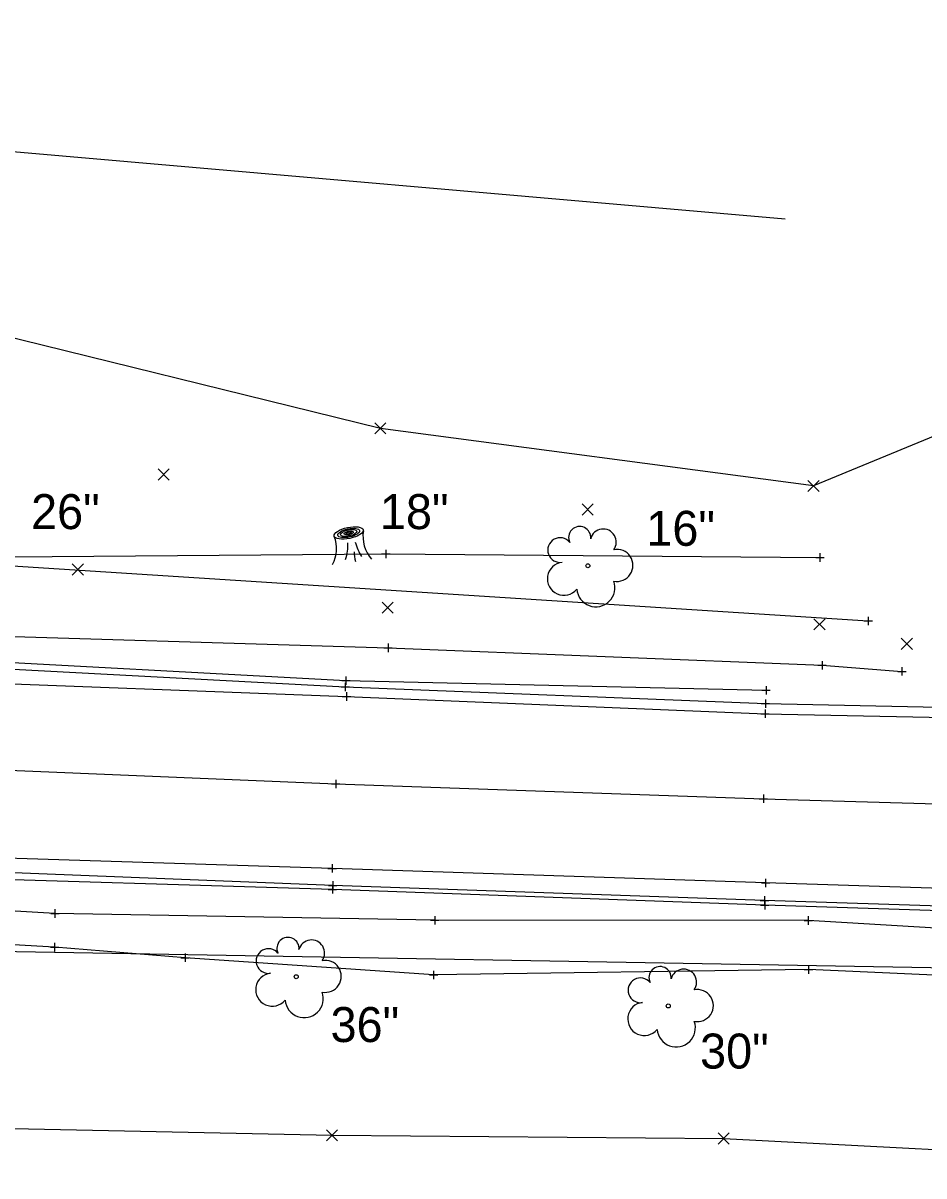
# Model space of a CAD drawing. Extents: x 2005176 to 2005823, y 572472 to 572942.
# Drawn here: x 2005639.9 to 2005747.1, y 572557 to 572694.3 of the extents above; entities that cross this region are included whole.
import ezdxf

# ---------------------------------------------------------------- set-up
doc = ezdxf.new("R2010")
doc.units = 0
for name, color, linetype in [('GE_X_Alignment_1000_Bearings', 7, 'Continuous'), ('GE_X_Alignment_100_Bearings', 7, 'Continuous'), ('GE_X_Alignment_100_Cardinal_Points', 7, 'Continuous'), ('GE_X_Alignment_100_Distances', 7, 'Continuous'), ('GE_X_Alignment_100_Stations', 7, 'Continuous'), ('GE_X_Alignment_500_Bearings', 7, 'Continuous'), ('GE_X_Alignment_500_Cardinal_Points', 7, 'Continuous'), ('GE_X_Alignment_500_Distances', 7, 'Continuous'), ('SC_Scratch10', 7, 'Continuous'), ('SC_Scratch8', 7, 'Continuous'), ('SV_P_Mon_Cells_Set', 7, 'Continuous'), ('SV_X_Random_Point', 7, 'Continuous'), ('SV_X_Shot_Marker', 7, 'Continuous'), ('SV_X_Terrain_Boundary', 7, 'Continuous'), ('UT_X_Overhead_Electric', 7, 'Continuous'), ('UT_X_Overhead_Telecom', 7, 'Continuous'), ('VG_X_Text', 7, 'Continuous')]:
    doc.layers.add(name, color=color, linetype=linetype)

msp = doc.modelspace()

# ---------------------------------------------------------------- linework, layer by layer
at = {"layer": 'GE_X_Alignment_1000_Bearings'}
msp.add_lwpolyline([(2005377.36, 572646.47), (2005740.51, 572623.1)], dxfattribs=at)
at = {"layer": 'GE_X_Alignment_100_Bearings'}
for points in [[(2005220.7, 572626.42), (2005272.19, 572624.71), (2005322.24, 572623.5), (2005370.59, 572622.7), (2005425.14, 572621.65), (2005477.36, 572620.84), (2005525.07, 572619.6), (2005576.7, 572617.86), (2005628.14, 572615.99), (2005678.39, 572614.09), (2005728.23, 572612.03), (2005777.04, 572611.02), (2005819.95, 572609.99)], [(2005818.64, 572588.97), (2005775.2, 572590.4), (2005728.29, 572591.88), (2005676.68, 572593.61), (2005626.55, 572595.19), (2005577.83, 572596.72), (2005526.97, 572598.44), (2005477.01, 572599.53), (2005423.67, 572600.7), (2005368.75, 572601.99), (2005321.74, 572602.99), (2005266.72, 572604.35), (2005220.03, 572605.66)]]:
    msp.add_lwpolyline(points, dxfattribs=at)
at = {"layer": 'GE_X_Alignment_100_Cardinal_Points'}
msp.add_lwpolyline([(2005220.5, 572615.99), (2005272.51, 572614.37), (2005322.2, 572613.2), (2005370.62, 572612.29), (2005424.94, 572611.27), (2005476.5, 572610.17), (2005524.32, 572608.79), (2005576.49, 572607.4), (2005627.69, 572605.77), (2005677.11, 572603.68), (2005728.03, 572601.92), (2005776.18, 572600.5), (2005820.14, 572599.28)], dxfattribs=at)
at = {"layer": 'GE_X_Alignment_100_Distances'}
for points in [[(2005220.68, 572626.38), (2005272.19, 572624.71), (2005322.24, 572623.5), (2005370.59, 572622.7), (2005425.14, 572621.65), (2005477.36, 572620.84), (2005525.07, 572619.6), (2005576.7, 572617.86), (2005628.14, 572615.99), (2005678.39, 572614.09), (2005728.23, 572612.03), (2005777.04, 572611.02), (2005820.02, 572609.9)], [(2005818.7, 572589.05), (2005775.2, 572590.4), (2005728.29, 572591.88), (2005676.68, 572593.61), (2005626.55, 572595.19), (2005577.83, 572596.72), (2005526.97, 572598.44), (2005477.01, 572599.53), (2005423.67, 572600.7), (2005368.75, 572601.99), (2005321.74, 572602.99), (2005266.72, 572604.35), (2005220.06, 572605.65)]]:
    msp.add_lwpolyline(points, dxfattribs=at)
at = {"layer": 'GE_X_Alignment_100_Stations'}
for points in [[(2005525.52, 572638.81), (2005532.8, 572636.84), (2005542.1, 572631.82), (2005552.86, 572627.27), (2005580.9, 572624.65), (2005628.27, 572621.55), (2005683.34, 572619.89), (2005735.02, 572617.81), (2005744.53, 572617.08)], [(2005818.32, 572583.75), (2005776.41, 572584.84), (2005733.38, 572587.41), (2005688.89, 572587.43), (2005643.67, 572588.24), (2005617.3, 572589.8), (2005601, 572590.26), (2005586.78, 572589.84), (2005574.29, 572588.4), (2005565.07, 572583.34)]]:
    msp.add_lwpolyline(points, dxfattribs=at)
at = {"layer": 'GE_X_Alignment_500_Bearings'}
msp.add_lwpolyline([(2005563.28, 572631.16), (2005581.34, 572632.07), (2005628.4, 572630.65), (2005683.07, 572631.08), (2005734.76, 572630.65)], dxfattribs=at)
at = {"layer": 'GE_X_Alignment_500_Cardinal_Points'}
msp.add_lwpolyline([(2005818.94, 572578.27), (2005776.52, 572579.63), (2005733.4, 572581.57), (2005688.76, 572580.93), (2005659.16, 572582.97), (2005643.63, 572584.23), (2005617.78, 572585.7), (2005598.98, 572587.73), (2005575.61, 572583.45)], dxfattribs=at)
at = {"layer": 'GE_X_Alignment_500_Distances'}
msp.add_lwpolyline([(2005220.4, 572616.04), (2005272.51, 572614.37), (2005322.2, 572613.2), (2005370.62, 572612.29), (2005424.94, 572611.27), (2005476.5, 572610.17), (2005524.32, 572608.79), (2005576.49, 572607.4), (2005627.69, 572605.77), (2005677.11, 572603.68), (2005728.03, 572601.92), (2005776.18, 572600.5), (2005820.14, 572599.26)], dxfattribs=at)
at = {"layer": 'SC_Scratch10'}
for points in [[(2005220.88, 572629.15), (2005272.14, 572627.64), (2005321.83, 572626.68), (2005370.65, 572626), (2005424.7, 572625.92), (2005476.69, 572625.33), (2005525.49, 572622.56), (2005576.48, 572620.99), (2005628.3, 572618.68), (2005678.32, 572615.98), (2005728.35, 572614.83)], [(2005818.55, 572585.94), (2005774.93, 572587.72), (2005728.19, 572589.23), (2005676.71, 572591.12), (2005626.89, 572592.62), (2005577.77, 572593.78), (2005527.62, 572595.75), (2005477.17, 572596.25), (2005467.62, 572596.6)]]:
    msp.add_lwpolyline(points, dxfattribs=at)
at = {"layer": 'SC_Scratch8'}
for points in [[(2005220.9, 572628.72), (2005272.16, 572627.13), (2005321.83, 572625.74), (2005370.81, 572625), (2005424.98, 572624.56), (2005477.31, 572623.7), (2005525.21, 572621.63), (2005576.56, 572620.01), (2005628.24, 572617.89), (2005678.25, 572615.23), (2005728.27, 572613.25), (2005777.12, 572612.24), (2005820.02, 572611.5)], [(2005818.66, 572586.64), (2005775.01, 572588.28), (2005728.16, 572589.79), (2005676.75, 572591.58), (2005626.73, 572593.57), (2005577.92, 572595.76), (2005527.42, 572597.32), (2005476.91, 572598.65), (2005423.43, 572599.27), (2005368.77, 572600.6), (2005321.59, 572601.67), (2005267.03, 572602.73), (2005220.03, 572603.93)]]:
    msp.add_lwpolyline(points, dxfattribs=at)
at = {"layer": 'SV_P_Mon_Cells_Set'}
for p, q in [((2005682.57, 572631.08), (2005683.57, 572631.08)), ((2005683.07, 572631.58), (2005683.07, 572630.58)), ((2005683.07, 572631.08), (2005683.07, 572631.08)), ((2005734.76, 572631.15), (2005734.76, 572630.15)), ((2005734.26, 572630.65), (2005735.26, 572630.65)), ((2005734.76, 572630.65), (2005734.76, 572630.65)), ((2005740.01, 572623.1), (2005741.01, 572623.1)), ((2005740.51, 572623.6), (2005740.51, 572622.6)), ((2005740.51, 572623.1), (2005740.51, 572623.1)), ((2005682.84, 572619.89), (2005683.84, 572619.89)), ((2005683.34, 572620.39), (2005683.34, 572619.39)), ((2005683.34, 572619.89), (2005683.34, 572619.89)), ((2005735.02, 572618.31), (2005735.02, 572617.31)), ((2005734.52, 572617.81), (2005735.52, 572617.81)), ((2005735.02, 572617.81), (2005735.02, 572617.81)), ((2005744.03, 572617.08), (2005745.03, 572617.08)), ((2005744.53, 572617.58), (2005744.53, 572616.58)), ((2005744.53, 572617.08), (2005744.53, 572617.08)), ((2005677.82, 572615.98), (2005678.82, 572615.98)), ((2005678.25, 572615.73), (2005678.25, 572614.73)), ((2005678.32, 572616.48), (2005678.32, 572615.48)), ((2005678.32, 572615.98), (2005678.32, 572615.98)), ((2005677.75, 572615.23), (2005678.75, 572615.23)), ((2005678.25, 572615.23), (2005678.25, 572615.23)), ((2005678.39, 572614.59), (2005678.39, 572613.59)), ((2005678.39, 572614.59), (2005678.39, 572613.59)), ((2005727.85, 572614.83), (2005728.85, 572614.83)), ((2005728.35, 572615.33), (2005728.35, 572614.33)), ((2005728.35, 572614.83), (2005728.35, 572614.83)), ((2005677.89, 572614.09), (2005678.89, 572614.09)), ((2005677.89, 572614.09), (2005678.89, 572614.09)), ((2005678.39, 572614.09), (2005678.39, 572614.09)), ((2005678.39, 572614.09), (2005678.39, 572614.09)), ((2005727.77, 572613.25), (2005728.77, 572613.25)), ((2005728.27, 572613.75), (2005728.27, 572612.75)), ((2005728.27, 572613.25), (2005728.27, 572613.25)), ((2005727.73, 572612.03), (2005728.73, 572612.03)), ((2005727.73, 572612.03), (2005728.73, 572612.03)), ((2005728.23, 572612.53), (2005728.23, 572611.53)), ((2005728.23, 572612.53), (2005728.23, 572611.53)), ((2005728.23, 572612.03), (2005728.23, 572612.03)), ((2005728.23, 572612.03), (2005728.23, 572612.03)), ((2005676.61, 572603.68), (2005677.61, 572603.68)), ((2005676.61, 572603.68), (2005677.61, 572603.68)), ((2005677.11, 572604.18), (2005677.11, 572603.18)), ((2005677.11, 572604.18), (2005677.11, 572603.18)), ((2005677.11, 572603.68), (2005677.11, 572603.68)), ((2005677.11, 572603.68), (2005677.11, 572603.68)), ((2005727.53, 572601.92), (2005728.53, 572601.92)), ((2005727.53, 572601.92), (2005728.53, 572601.92)), ((2005728.03, 572602.42), (2005728.03, 572601.42)), ((2005728.03, 572602.42), (2005728.03, 572601.42)), ((2005728.03, 572601.92), (2005728.03, 572601.92)), ((2005728.03, 572601.92), (2005728.03, 572601.92)), ((2005676.18, 572593.61), (2005677.18, 572593.61)), ((2005676.18, 572593.61), (2005677.18, 572593.61)), ((2005676.68, 572594.11), (2005676.68, 572593.11)), ((2005676.68, 572594.11), (2005676.68, 572593.11)), ((2005676.68, 572593.61), (2005676.68, 572593.61)), ((2005676.68, 572593.61), (2005676.68, 572593.61)), ((2005728.29, 572592.38), (2005728.29, 572591.38)), ((2005728.29, 572592.38), (2005728.29, 572591.38)), ((2005676.21, 572591.12), (2005677.21, 572591.12)), ((2005676.25, 572591.58), (2005677.25, 572591.58)), ((2005676.71, 572591.62), (2005676.71, 572590.62)), ((2005676.71, 572591.12), (2005676.71, 572591.12)), ((2005676.75, 572592.08), (2005676.75, 572591.08)), ((2005676.75, 572591.58), (2005676.75, 572591.58)), ((2005727.79, 572591.88), (2005728.79, 572591.88)), ((2005727.79, 572591.88), (2005728.79, 572591.88)), ((2005728.29, 572591.88), (2005728.29, 572591.88)), ((2005728.29, 572591.88), (2005728.29, 572591.88)), ((2005727.66, 572589.79), (2005728.66, 572589.79)), ((2005728.16, 572590.29), (2005728.16, 572589.29)), ((2005728.16, 572589.79), (2005728.16, 572589.79)), ((2005728.19, 572589.73), (2005728.19, 572588.73)), ((2005643.17, 572588.24), (2005644.17, 572588.24)), ((2005643.67, 572588.74), (2005643.67, 572587.74)), ((2005643.67, 572588.24), (2005643.67, 572588.24)), ((2005727.69, 572589.23), (2005728.69, 572589.23)), ((2005728.19, 572589.23), (2005728.19, 572589.23)), ((2005688.39, 572587.43), (2005689.39, 572587.43)), ((2005688.89, 572587.93), (2005688.89, 572586.93)), ((2005688.89, 572587.43), (2005688.89, 572587.43)), ((2005732.88, 572587.41), (2005733.88, 572587.41)), ((2005733.38, 572587.91), (2005733.38, 572586.91)), ((2005733.38, 572587.41), (2005733.38, 572587.41)), ((2005643.13, 572584.23), (2005644.13, 572584.23)), ((2005643.63, 572584.73), (2005643.63, 572583.73)), ((2005643.63, 572584.23), (2005643.63, 572584.23)), ((2005658.66, 572582.97), (2005659.66, 572582.97)), ((2005659.16, 572583.47), (2005659.16, 572582.47)), ((2005659.16, 572582.97), (2005659.16, 572582.97)), ((2005688.76, 572581.43), (2005688.76, 572580.43)), ((2005732.9, 572581.57), (2005733.9, 572581.57)), ((2005733.4, 572582.07), (2005733.4, 572581.07)), ((2005733.4, 572581.57), (2005733.4, 572581.57)), ((2005688.26, 572580.93), (2005689.26, 572580.93)), ((2005688.76, 572580.93), (2005688.76, 572580.93))]:
    msp.add_line(p, q, dxfattribs=at)
at = {"layer": 'SV_X_Random_Point'}
for p, q in [((2005681.76, 572645.37), (2005683.09, 572646.7)), ((2005681.76, 572646.7), (2005683.09, 572645.37)), ((2005655.96, 572639.88), (2005657.29, 572641.21)), ((2005655.96, 572641.21), (2005657.29, 572639.88)), ((2005733.34, 572638.5), (2005734.67, 572639.83)), ((2005733.34, 572639.83), (2005734.67, 572638.5)), ((2005706.44, 572635.71), (2005707.77, 572637.05)), ((2005706.44, 572637.05), (2005707.77, 572635.71)), ((2005645.73, 572628.55), (2005647.06, 572629.88)), ((2005645.73, 572629.88), (2005647.06, 572628.55)), ((2005682.63, 572624), (2005683.96, 572625.33)), ((2005682.63, 572625.33), (2005683.96, 572624)), ((2005734.04, 572622.02), (2005735.37, 572623.36)), ((2005734.04, 572623.36), (2005735.37, 572622.02)), ((2005744.45, 572619.7), (2005745.78, 572621.03)), ((2005744.45, 572621.03), (2005745.78, 572619.7)), ((2005676, 572561.15), (2005677.33, 572562.49)), ((2005676, 572562.49), (2005677.33, 572561.15)), ((2005722.63, 572560.76), (2005723.97, 572562.1)), ((2005722.63, 572562.1), (2005723.97, 572560.76))]:
    msp.add_line(p, q, dxfattribs=at)
at = {"layer": 'SV_X_Shot_Marker'}
msp.add_line((2005679.03, 572632.06), (2005679.03, 572632.06), dxfattribs=at)
for centre in [(2005707.13, 572629.66), (2005672.4, 572580.71), (2005716.7, 572577.23)]:
    msp.add_circle(centre, 0.24, dxfattribs=at)
for centre, radius, start, end in [((2005684.64, 572633.2), 4.29, 171.4106, 219.9194), ((2005706.15, 572633.03), 1.32, 354.0047, 205.9741), ((2005708.96, 572632.49), 1.55, 323.83, 165.0376), ((2005673.2, 572631.72), 4, 331.5338, 20.9269), ((2005673.51, 572632.09), 5.05, 340.7938, 3.5481), ((2005685.54, 572634.12), 6.32, 194.9653, 212.1216), ((2005703.82, 572631.53), 1.47, 39.0625, 279.5412), ((2005682.93, 572631.26), 3.64, 178.7926, 197.1224), ((2005710.59, 572629.7), 1.91, 259.1453, 101.4596), ((2005704.28, 572628.11), 1.97, 96.1722, 320.5737), ((2005708.08, 572627.06), 2.28, 184.9476, 19.4572), ((2005671.42, 572584.08), 1.32, 354.0047, 205.9741), ((2005669.09, 572582.58), 1.47, 39.0625, 279.5412), ((2005674.23, 572583.54), 1.55, 323.83, 165.0376), ((2005675.86, 572580.75), 1.91, 259.1453, 101.4596), ((2005715.72, 572580.6), 1.32, 354.0047, 205.9741), ((2005718.53, 572580.06), 1.55, 323.83, 165.0376), ((2005669.55, 572579.17), 1.97, 96.1722, 320.5737), ((2005713.39, 572579.09), 1.47, 39.0625, 279.5412), ((2005673.35, 572578.11), 2.28, 184.9476, 19.4572), ((2005720.16, 572577.27), 1.91, 259.1453, 101.4596), ((2005713.85, 572575.68), 1.97, 96.1722, 320.5737), ((2005717.65, 572574.62), 2.28, 184.9476, 19.4572)]:
    msp.add_arc(centre, radius, start, end, dxfattribs=at)
for major_axis in [(1.74, 0.37), (1.3, 0.28), (0.976, 0.211), (0.549, 0.119), (0.309, 0.067)]:
    msp.add_ellipse((2005678.65, 572633.57), major_axis=major_axis, ratio=0.36865, dxfattribs=at)
at = {"layer": 'SV_X_Terrain_Boundary'}
msp.add_lwpolyline([(2005632.87, 572562.76), (2005676.67, 572561.82), (2005723.3, 572561.43), (2005770.44, 572558.96), (2005815.9, 572556.98), (2005818.94, 572578.27), (2005818.32, 572583.75), (2005818.55, 572585.94), (2005818.7, 572589.05), (2005820.02, 572609.9), (2005820.38, 572612.97), (2005821.63, 572615.44), (2005821.52, 572622.31), (2005822.21, 572629.54), (2005821.61, 572640.59), (2005763.54, 572647.6), (2005754.32, 572647.56), (2005734.01, 572639.17), (2005682.42, 572646.03), (2005631.48, 572658.58)], dxfattribs=at)
at = {"layer": 'UT_X_Overhead_Electric'}
msp.add_line((2005462.76, 572694.31), (2005730.63, 572670.98), dxfattribs=at)
at = {"layer": 'UT_X_Overhead_Telecom'}
msp.add_line((2005612.94, 572584.19), (2005774.39, 572581.34), dxfattribs=at)

# ---------------------------------------------------------------- texts
at = {"layer": 'VG_X_Text'}
for s, p in [('26"', (2005640.83, 572634.03)), ('18"', (2005682.37, 572634.03)), ('16"', (2005714.09, 572632.04)), ('36"', (2005676.49, 572572.93)), ('30"', (2005720.49, 572569.77))]:
    msp.add_text(s, height=4.167, dxfattribs=at).set_placement(p)

doc.saveas('drawing.dxf')
